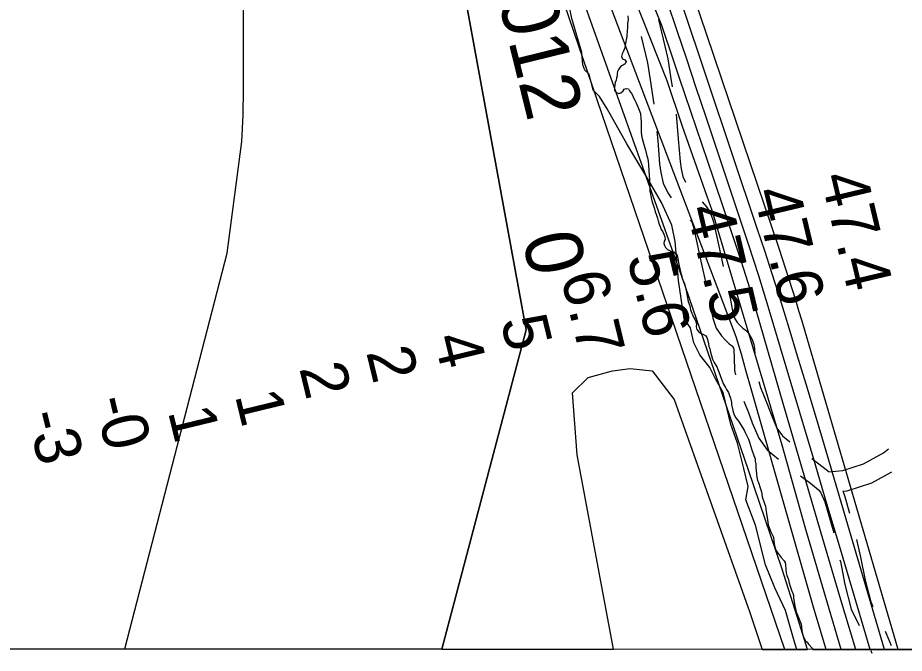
# Model space of a CAD drawing. Extents: x 3250478 to 3288318, y 788638 to 816472.
# Drawn here: x 3278442 to 3279729, y 794010 to 794932 of the extents above; entities that cross this region are included whole.
import ezdxf

# ---------------------------------------------------------------- set-up
doc = ezdxf.new("R2010")
doc.units = 0
for name, color, linetype in [('V-GRID-FRAM', 7, 'Continuous'), ('V-RIVR-EDGE', 7, 'Continuous'), ('V-RIVR-IDEN', 7, 'Continuous'), ('V-RIVR-RANG', 7, 'Continuous'), ('V-ROAD-CNTR', 7, 'Continuous'), ('V-SITE-VEGE', 7, 'Continuous'), ('V-TOPO-DPTH', 7, 'Continuous'), ('V-TOPO-MAJR', 7, 'Continuous'), ('V-TOPO-MINR', 7, 'Continuous'), ('V-TOPO-MINR-IDEN', 7, 'Continuous'), ('V-TOPO-WATR', 7, 'Continuous')]:
    doc.layers.add(name, color=color, linetype=linetype)

msp = doc.modelspace()

# ---------------------------------------------------------------- linework, layer by layer
at = {"layer": 'V-GRID-FRAM'}
msp.add_lwpolyline([(3254649.6, 812209.1), (3286070.1, 812200), (3286072.7, 794013.5), (3254636.4, 794022.7), (3254649.6, 812209.1)], dxfattribs=at)
at = {"layer": 'V-RIVR-EDGE'}
msp.add_lwpolyline([(3279573, 794015.4), (3279570, 794024.3), (3279556.2, 794071.7), (3279541, 794104.8), (3279527.2, 794138.3), (3279512.6, 794195.7), (3279498.8, 794232.7), (3279502.3, 794251.8), (3279495.8, 794277.9), (3279486.8, 794314.9), (3279476.9, 794341.8), (3279466.1, 794388.4), (3279455.3, 794407.1), (3279446.6, 794424.5), (3279431.9, 794442.8), (3279423.3, 794460.6), (3279418.5, 794482.4), (3279409.4, 794495.4), (3279401.3, 794551.1), (3279396.2, 794607.6), (3279391.5, 794631.1), (3279376.4, 794664.2), (3279353.9, 794703.4), (3279326.2, 794749.5), (3279297.6, 794800), (3279286.4, 794818.3), (3279277.2, 794827.4), (3279271.7, 794850.5), (3279265.1, 794856.2), (3279262.1, 794864), (3279260.9, 794881.8), (3279246.2, 794931.4), (3279237.6, 794974.5)], dxfattribs=at)
at = {"layer": 'V-ROAD-CNTR'}
msp.add_line((3279680.1, 794013.8), (3279681.7, 794009.7), dxfattribs=at)
for points in [[(3279372.1, 794930), (3279385.7, 794872.7), (3279389.7, 794847.1), (3279391.9, 794832)], [(3279347.1, 794905.3), (3279356.2, 794866.9), (3279360, 794842.5), (3279365.3, 794807.1)], [(3279397.5, 794792.4), (3279400.8, 794756.5), (3279403.4, 794723.9), (3279405.2, 794713.2), (3279407.6, 794701.7), (3279411.3, 794693.9)], [(3279369.7, 794767.3), (3279370.9, 794753.9), (3279373.6, 794720.2), (3279375.7, 794707.6), (3279379, 794692.1), (3279385.6, 794678.2), (3279390.6, 794671.1)], [(3279435.4, 794665.1), (3279441.7, 794658), (3279447.7, 794648.8), (3279451.7, 794635.9), (3279463, 794585.5), (3279466, 794571.5)], [(3279418.2, 794639.1), (3279420.3, 794635.9), (3279422.7, 794628.2), (3279433.7, 794579.1), (3279441.7, 794542.2)], [(3279474.5, 794532.4), (3279474.9, 794530.6), (3279480.1, 794503.8), (3279482.9, 794495.3), (3279486.7, 794489.7), (3279490.3, 794485.9), (3279494.6, 794481.7), (3279499.6, 794477.7), (3279503.6, 794473.1), (3279505.5, 794469.8), (3279508.2, 794465.1), (3279510.5, 794458.2), (3279511.4, 794452.1), (3279511.7, 794443.4)], [(3279449.6, 794503), (3279451, 794496.1), (3279455.7, 794481.9), (3279463.3, 794470.7), (3279468.9, 794464.9), (3279474.6, 794459.2), (3279478.9, 794455.9), (3279479.1, 794455.5), (3279479.5, 794455), (3279480.7, 794452.8), (3279481.3, 794451.1), (3279481.5, 794449.5), (3279481.8, 794439.3), (3279482.2, 794420.2), (3279484, 794413.8)], [(3279517.8, 794404.2), (3279520.2, 794395.8), (3279525.4, 794382.5), (3279530.4, 794370.6), (3279536.2, 794355.2), (3279543.8, 794336.6), (3279551.9, 794325.6), (3279562.5, 794316.7)], [(3279495.8, 794375.6), (3279497.6, 794371.1), (3279502.5, 794359.5), (3279508.2, 794344.3), (3279517.4, 794321.9), (3279529.8, 794304.9), (3279546, 794291.5)], [(3279619.2, 794273), (3279639.4, 794275.1), (3279669.5, 794284.9), (3279698.5, 794300.7), (3279705.8, 794306.4)], [(3279594.5, 794292.7), (3279611.1, 794280.1), (3279619.7, 794273.1)], [(3279639.3, 794244.9), (3279645.6, 794245.6), (3279681.5, 794257.2), (3279710.6, 794273.1)], [(3279578, 794267.5), (3279592.5, 794256.6), (3279604.3, 794246.9), (3279606.9, 794243.7), (3279609.1, 794239.5), (3279612, 794233), (3279613.2, 794229.7), (3279626.5, 794184.5)], [(3279639.6, 794244.9), (3279640, 794244.1), (3279641.8, 794238.8), (3279649.3, 794213.3)], [(3279659.5, 794174.7), (3279665.3, 794149.2), (3279671.8, 794116.1), (3279679.9, 794084.3), (3279683.2, 794077.7)], [(3279635.3, 794145.5), (3279635.9, 794143), (3279642.6, 794109.5), (3279651.6, 794073.9), (3279663.4, 794050.1)], [(3279700.8, 794041.8), (3279702.5, 794038.3), (3279709.5, 794021.1)]]:
    msp.add_lwpolyline(points, dxfattribs=at)
at = {"layer": 'V-SITE-VEGE'}
for p, q in [((3279328.1, 794929.5), (3279327.3, 794924.2)), ((3279327.6, 794935), (3279328.1, 794929.5)), ((3279327.2, 794918.4), (3279326.4, 794913.2)), ((3279327.3, 794924.2), (3279327.2, 794918.4)), ((3279326.3, 794905.8), (3279323.7, 794892.6)), ((3279326.4, 794913.2), (3279326.3, 794905.8)), ((3279323.2, 794888.6), (3279321.5, 794883.7)), ((3279323.7, 794892.6), (3279323.2, 794888.6)), ((3279319.5, 794880.2), (3279318.3, 794876.2)), ((3279318.3, 794876.2), (3279320, 794872.9)), ((3279321.5, 794883.7), (3279319.5, 794880.2)), ((3279318.1, 794862.5), (3279315.8, 794860.2)), ((3279320.9, 794863.8), (3279318.1, 794862.5)), ((3279320, 794872.9), (3279323.1, 794871.2)), ((3279323.9, 794865.7), (3279320.9, 794863.8)), ((3279323.1, 794871.2), (3279325.3, 794868.8)), ((3279325.3, 794868.8), (3279323.9, 794865.7)), ((3279312.6, 794854.3), (3279312.1, 794851.3)), ((3279312.1, 794851.3), (3279312.1, 794848.2)), ((3279314, 794857.4), (3279312.6, 794854.3)), ((3279315.8, 794860.2), (3279314, 794857.4)), ((3279309.1, 794838.6), (3279308.1, 794831.6)), ((3279310.8, 794841.7), (3279309.1, 794838.6)), ((3279311.3, 794844.8), (3279310.8, 794841.7)), ((3279312.1, 794848.2), (3279311.3, 794844.8)), ((3279308.1, 794831.6), (3279308.2, 794826.7)), ((3279308.2, 794826.7), (3279311, 794823.7)), ((3279311, 794823.7), (3279314.5, 794822.3)), ((3279314.5, 794822.3), (3279317.2, 794823.6)), ((3279317.2, 794823.6), (3279320.8, 794826.1)), ((3279320.8, 794826.1), (3279322.2, 794828.9)), ((3279322.2, 794828.9), (3279325.3, 794829.6)), ((3279325.3, 794829.6), (3279328.6, 794829.1)), ((3279328.6, 794829.1), (3279330.2, 794826.4)), ((3279330.2, 794826.4), (3279332.8, 794822.5)), ((3279332.8, 794822.5), (3279334.7, 794819.2)), ((3279334.7, 794819.2), (3279335.8, 794816.2)), ((3279335.8, 794816.2), (3279337.7, 794812.9)), ((3279337.7, 794812.9), (3279339, 794809.8)), ((3279339, 794809.8), (3279342.3, 794803.2)), ((3279342.3, 794803.2), (3279344.9, 794795.9)), ((3279344.9, 794795.9), (3279346.2, 794793.2)), ((3279346.2, 794793.2), (3279346.5, 794785.6)), ((3279346.5, 794785.6), (3279346.9, 794782.2)), ((3279347, 794776.4), (3279346.7, 794766.6)), ((3279346.9, 794782.2), (3279347, 794776.4)), ((3279346.7, 794766.6), (3279347.2, 794761.4)), ((3279347.2, 794761.4), (3279348.2, 794756.9)), ((3279348.2, 794756.9), (3279349.9, 794751.7)), ((3279349.9, 794751.7), (3279353.3, 794740.2)), ((3279353.3, 794740.2), (3279355.1, 794732)), ((3279355.1, 794732), (3279356.5, 794727.4)), ((3279356.5, 794727.4), (3279357.2, 794723.2)), ((3279357.2, 794723.2), (3279357.6, 794719.5)), ((3279357.6, 794719.5), (3279357.9, 794710.1)), ((3279357.9, 794710.1), (3279358.9, 794697.2)), ((3279358.9, 794697.2), (3279359.4, 794680.7)), ((3279359.4, 794680.7), (3279360.4, 794676.5)), ((3279360.4, 794676.5), (3279362.6, 794666.7)), ((3279362.6, 794666.7), (3279366.3, 794655.2)), ((3279366.3, 794655.2), (3279367.3, 794650.7)), ((3279367.3, 794650.7), (3279368.7, 794647.3)), ((3279368.7, 794647.3), (3279370.4, 794641.3)), ((3279370.4, 794641.3), (3279371.7, 794637.6)), ((3279371.7, 794637.6), (3279373.1, 794632.5)), ((3279373.1, 794632.5), (3279374.4, 794629.5)), ((3279374.4, 794629.5), (3279376.1, 794624.9)), ((3279376.1, 794624.9), (3279378.3, 794621.6)), ((3279378.3, 794621.6), (3279379.9, 794618.3)), ((3279379.9, 794618.3), (3279381.3, 794614.1)), ((3279380.2, 794607.9), (3279379.7, 794604.8)), ((3279379.7, 794604.8), (3279380.7, 794601.8)), ((3279381.7, 794610.7), (3279380.2, 794607.9)), ((3279381.3, 794614.1), (3279381.7, 794610.7)), ((3279380.7, 794601.8), (3279382.4, 794598.8)), ((3279382.4, 794598.8), (3279384.9, 794596.1)), ((3279384.9, 794596.1), (3279391.1, 794593.2)), ((3279391.1, 794593.2), (3279394.5, 794592.4)), ((3279394.5, 794592.4), (3279397.3, 794590.1)), ((3279397.3, 794590.1), (3279399.2, 794587.4)), ((3279399.2, 794587.4), (3279400.7, 794579.8)), ((3279400.7, 794579.8), (3279401.1, 794576.4)), ((3279401.1, 794576.4), (3279404.3, 794561.5)), ((3279404.3, 794561.5), (3279405.9, 794557)), ((3279405.9, 794557), (3279406.6, 794553.9)), ((3279406.6, 794553.9), (3279408.3, 794549.4)), ((3279408.3, 794549.4), (3279409.6, 794546.7)), ((3279409.6, 794546.7), (3279410.7, 794542.1)), ((3279410.7, 794542.1), (3279411.7, 794538.5)), ((3279411.7, 794538.5), (3279412.5, 794533.6)), ((3279412.5, 794533.6), (3279413.5, 794528.1)), ((3279413.5, 794528.1), (3279415.3, 794520.5)), ((3279415.3, 794520.5), (3279417.3, 794514.2)), ((3279417.3, 794514.2), (3279418.7, 794508.4)), ((3279418.7, 794508.4), (3279423, 794497.8)), ((3279423, 794497.8), (3279424.6, 794494.8)), ((3279424.6, 794494.8), (3279426.3, 794491.5)), ((3279426.3, 794491.5), (3279427, 794488.1)), ((3279427, 794488.1), (3279426.8, 794483.6)), ((3279426.8, 794483.6), (3279427.8, 794479.9)), ((3279427.8, 794479.9), (3279430.4, 794476.3)), ((3279430.4, 794476.3), (3279433.2, 794474.6)), ((3279433.2, 794474.6), (3279437.5, 794472.6)), ((3279437.5, 794472.6), (3279440.7, 794470.8)), ((3279440.7, 794470.8), (3279442.3, 794468.1)), ((3279442.3, 794468.1), (3279443.3, 794465.1)), ((3279443.3, 794465.1), (3279444.7, 794459)), ((3279444.7, 794459), (3279445.1, 794455)), ((3279445.1, 794455), (3279446.4, 794452)), ((3279446.4, 794452), (3279447.5, 794447.1)), ((3279447.5, 794447.1), (3279450.2, 794436.8)), ((3279450.2, 794436.8), (3279452.8, 794431.7)), ((3279452.8, 794431.7), (3279457, 794424.8)), ((3279457, 794424.8), (3279458, 794421.8)), ((3279458, 794421.8), (3279459.4, 794418.4)), ((3279459.4, 794418.4), (3279463.4, 794407.5)), ((3279463.4, 794407.5), (3279466.6, 794400.3)), ((3279466.6, 794400.3), (3279469.2, 794395.5)), ((3279469.2, 794395.5), (3279470.5, 794392.8)), ((3279470.5, 794392.8), (3279473.4, 794388.3)), ((3279473.4, 794388.3), (3279474.7, 794385.2)), ((3279474.7, 794385.2), (3279476.4, 794380.1)), ((3279476.4, 794380.1), (3279477.8, 794374)), ((3279477.8, 794374), (3279477.9, 794371)), ((3279477.9, 794371), (3279479, 794366.7)), ((3279479, 794366.7), (3279479.7, 794362.4)), ((3279479.7, 794362.4), (3279480.7, 794358.8)), ((3279480.7, 794358.8), (3279481.7, 794355.8)), ((3279481.7, 794355.8), (3279484.3, 794351.6)), ((3279484.3, 794351.6), (3279488.1, 794346.8)), ((3279488.1, 794346.8), (3279496.5, 794333.6)), ((3279496.5, 794333.6), (3279497.8, 794330.5)), ((3279497.8, 794330.5), (3279500.4, 794325.4)), ((3279500.4, 794325.4), (3279502.7, 794320.6)), ((3279502.7, 794320.6), (3279504, 794316.4)), ((3279504, 794316.4), (3279506.8, 794306.6)), ((3279506.8, 794306.6), (3279507.8, 794303.6)), ((3279507.8, 794303.6), (3279510.4, 794297)), ((3279510.4, 794297), (3279512.1, 794291.8)), ((3279512.1, 794291.8), (3279512.5, 794288.5)), ((3279512.5, 794288.5), (3279513.3, 794284.2)), ((3279513.3, 794284.2), (3279513.1, 794279.3)), ((3279513.1, 794279.3), (3279514.7, 794265.6)), ((3279514.7, 794265.6), (3279515.8, 794260.7)), ((3279515.8, 794260.7), (3279517.1, 794257.7)), ((3279517.1, 794257.7), (3279519.5, 794250.1)), ((3279519.5, 794250.1), (3279521.5, 794244.1)), ((3279521.5, 794244.1), (3279522.3, 794237)), ((3279522.3, 794237), (3279526, 794227.4)), ((3279526, 794227.4), (3279527.3, 794223.4)), ((3279527.3, 794223.4), (3279527.8, 794219.2)), ((3279527.8, 794219.2), (3279528.5, 794215.5)), ((3279528.5, 794215.5), (3279530.1, 794203.3)), ((3279530.1, 794203.3), (3279531.3, 794196)), ((3279531.3, 794196), (3279534.4, 794187)), ((3279534.4, 794187), (3279537.2, 794182.2)), ((3279537.2, 794182.2), (3279539.1, 794178.4)), ((3279539.1, 794178.4), (3279539.3, 794172.6)), ((3279539.3, 794172.6), (3279540.2, 794165.9)), ((3279540.2, 794165.9), (3279542.4, 794159.6)), ((3279542.4, 794159.6), (3279544, 794156.4)), ((3279544, 794156.4), (3279550, 794149)), ((3279550, 794149), (3279554.4, 794143.8)), ((3279554.4, 794143.8), (3279555.9, 794141.3)), ((3279555.9, 794141.3), (3279556.5, 794138.1)), ((3279556.5, 794138.1), (3279556.8, 794131.4)), ((3279556.8, 794131.4), (3279557.4, 794126.3)), ((3279557.4, 794126.3), (3279558.3, 794122.8)), ((3279558.3, 794122.8), (3279560.5, 794116.7)), ((3279560.5, 794116.7), (3279561.1, 794113.5)), ((3279561.1, 794113.5), (3279563.6, 794105.8)), ((3279563.6, 794105.8), (3279565.7, 794100.1)), ((3279565.7, 794100.1), (3279567, 794097.2)), ((3279567, 794097.2), (3279567.9, 794093.7)), ((3279567.9, 794093.7), (3279567.9, 794089.9)), ((3279567.9, 794089.9), (3279569.1, 794084.8)), ((3279569.1, 794084.8), (3279569.4, 794080.6)), ((3279569.4, 794080.6), (3279571.8, 794070.1)), ((3279571.8, 794070.1), (3279575.3, 794061.8)), ((3279575.3, 794061.8), (3279579, 794052.2)), ((3279579, 794052.2), (3279579.6, 794048)), ((3279579.6, 794048), (3279580.2, 794042)), ((3279580.2, 794042), (3279581.4, 794036.6)), ((3279581.4, 794036.6), (3279583.6, 794031.1)), ((3279583.6, 794031.1), (3279585.5, 794027.9)), ((3279585.5, 794027.9), (3279588, 794026)), ((3279588, 794026), (3279589.6, 794023.1)), ((3279589.6, 794023.1), (3279595.9, 794016)), ((3279595.9, 794016), (3279596.1, 794015.4)), ((3279596.1, 794015.4), (3286072.7, 794013.5))]:
    msp.add_line(p, q, dxfattribs=at)
at = {"layer": 'V-TOPO-DPTH'}
for points in [[(3279522.7, 794015.4), (3279588.3, 794015.4), (3279573.8, 794061.7), (3279550.8, 794133.3), (3279527, 794204.6), (3279502.7, 794275.7), (3279411.4, 794541.6), (3279128.4, 795335.7), (3279124.3, 795347.8), (3278841.2, 796159.2)], [(3279057.6, 794015.6), (3278260.3, 794016.3), (3278403.9, 794831.3), (3278416.4, 794942.1), (3278416.5, 794961.6), (3278416.1, 794981.1), (3278415.2, 795000.6), (3278414, 795020), (3278405.8, 795125.3), (3278400.6, 795197.4), (3278395.9, 795269.5), (3278391.9, 795341.7), (3278388.5, 795413.9), (3278377.3, 795677.1), (3278398.9, 795790.4), (3278405.1, 795830.1), (3278409.6, 795870), (3278411.5, 795910.1), (3278411.7, 795950.3), (3278410.5, 795990.6), (3278409.3, 796030.9), (3278408.8, 796048.2)], [(3278859.6, 795871.1), (3278877.2, 795822.7), (3278881, 795812.1), (3278884.7, 795801.4), (3278888.4, 795790.7), (3278892, 795780), (3278914.1, 795712.9), (3278928.2, 795668.4), (3278941.5, 795623.7), (3278953.6, 795578.7), (3278965, 795533.5), (3279061.2, 795129.2), (3279180.3, 794479.5), (3279057.6, 794015.6)], [(3278859.6, 795871.1), (3278877.2, 795822.7), (3278881, 795812.1), (3278884.7, 795801.4), (3278888.4, 795790.7), (3278892, 795780), (3278914.1, 795712.9), (3278928.2, 795668.4), (3278941.5, 795623.7), (3278953.6, 795578.7), (3278965, 795533.5), (3279061.2, 795129.2), (3279180.3, 794479.5), (3279057.6, 794015.6), (3279306.6, 794015.5)], [(3279522.7, 794015.4), (3279306.6, 794015.5), (3279253.9, 794298), (3279247.5, 794387.7), (3279269.9, 794410.2), (3279305.2, 794419.8), (3279330.8, 794423), (3279362.8, 794419.8), (3279394.9, 794378.1), (3279503.9, 794070.3), (3279522.7, 794015.4)], [(3279306.6, 794015.5), (3279253.9, 794298), (3279247.5, 794387.7), (3279269.9, 794410.2), (3279305.2, 794419.8), (3279330.8, 794423), (3279362.8, 794419.8), (3279394.9, 794378.1), (3279503.9, 794070.3), (3279522.7, 794015.4)]]:
    msp.add_lwpolyline(points, dxfattribs=at)
at = {"layer": 'V-TOPO-MAJR'}
msp.add_lwpolyline([(3279658.2, 794015.4), (3279635.3, 794092.1), (3279607.9, 794184.3), (3279580.8, 794276.6), (3279554, 794368.9), (3279508.4, 794526.2), (3279504.4, 794539.9), (3279495.9, 794567.3), (3279491.4, 794580.9), (3279468.1, 794650.8), (3279451.9, 794699.3), (3279435.6, 794747.9), (3279419.2, 794796.3), (3279402.7, 794844.8), (3279394.3, 794869.5), (3279377.1, 794921.1), (3279092.3, 795626.9), (3279080.4, 795649.8), (3279069.9, 795673.5), (3279027.2, 795783.4), (3279018.2, 795806.7), (3279009.4, 795830.1), (3279000.8, 795853.6)], dxfattribs=at)
at = {"layer": 'V-TOPO-MINR'}
for points in [[(3279588.3, 794015.4), (3279573.8, 794061.7), (3279550.8, 794133.3), (3279527, 794204.6), (3279502.7, 794275.7), (3279411.4, 794541.6), (3279128.4, 795335.7), (3279124.3, 795347.8), (3278841.2, 796159.2)], [(3279555.5, 794015.4), (3279153.9, 795192.3), (3279152.6, 795194.3), (3279151.6, 795196.4), (3279150.7, 795198.6), (3279149.8, 795200.8), (3279149, 795203.1), (3279148.3, 795205.4), (3278840.2, 796077.4)], [(3279637.1, 794015.4), (3279619.5, 794074.3), (3279585.1, 794193), (3279551.3, 794311.9), (3279449.8, 794652.4), (3279442.7, 794672.9), (3279407.1, 794774.4), (3279384.5, 794841), (3279017.6, 795767.2), (3279006.9, 795797.1), (3278996.1, 795826.9), (3278985.5, 795856.8)], [(3279615.1, 794015.4), (3279597, 794076.9), (3279563.9, 794191.8), (3279506.7, 794393.7), (3279499.5, 794418.9), (3279492.3, 794444.1), (3279484.9, 794469.3), (3279117.5, 795435.9), (3279110, 795454.4), (3279103.1, 795473.2), (3278991.2, 795801.4), (3278987.4, 795812.6), (3278983.5, 795823.8), (3278979.6, 795835.1)], [(3279679.3, 794015.4), (3279636.2, 794160.7), (3279616.5, 794226.9), (3279596.8, 794293.1), (3279577.1, 794359.3), (3279557.4, 794425.5), (3279531.4, 794513.1), (3279524.6, 794535.5), (3279517.7, 794557.8), (3279510.5, 794580.1), (3279503.2, 794602.2), (3279440.7, 794789.4), (3279426.9, 794830.7), (3279413, 794872.1), (3279399.2, 794913.5), (3279385.3, 794954.9), (3279382, 794964.8), (3279370, 795001.3), (3279057.9, 795749.5), (3279036.6, 795800.1), (3279029.8, 795816.8), (3279023.1, 795833.5)], [(3279699.9, 794015.4), (3279610.3, 794319.6), (3279598.2, 794360.1), (3279586.2, 794400.6), (3279573.9, 794441.1), (3279561.7, 794481.6), (3279556.3, 794499.2), (3279546.5, 794530.8), (3279536.5, 794562.3), (3279526.3, 794593.8), (3279515.9, 794625.2), (3279405.9, 794952.9), (3279397.5, 794977.9), (3279389.2, 795002.9), (3279380.9, 795027.9), (3279372.6, 795052.9), (3279370.2, 795060.3), (3279363.3, 795081.7), (3279052.5, 795802.8), (3279045.8, 795817.3), (3279041.4, 795827.1), (3279037.3, 795836.9)], [(3279720, 794015.4), (3279584.9, 794476.8), (3279580.4, 794492), (3279575.9, 794507.1), (3279571.2, 794522.2), (3279566.6, 794537.2), (3279561.8, 794552.3), (3279557, 794567.3), (3279552, 794582.3), (3279547.1, 794597.2), (3279369.2, 795124), (3279366.7, 795131.4), (3279364.3, 795138.7), (3279361.9, 795146.1), (3279359.5, 795153.4), (3279358.6, 795156), (3279356.7, 795162.1), (3279354.7, 795168.2), (3279352.9, 795174.3), (3279351, 795180.4), (3279349.3, 795186), (3279056, 795831.8)], [(3278597.9, 794016.3), (3278746.4, 794590.5), (3278767.7, 794752.8), (3278769.3, 794790.9), (3278769.9, 794829.1), (3278769.7, 795058.1), (3278753.7, 795211.3), (3278749.1, 795241.9)]]:
    msp.add_lwpolyline(points, dxfattribs=at)
at = {"layer": 'V-TOPO-WATR'}
for points in [[(3279057.6, 794015.6), (3279180.3, 794479.5), (3279061.2, 795129.2), (3278965, 795533.5), (3278953.6, 795578.7), (3278941.5, 795623.7), (3278928.2, 795668.4), (3278914.1, 795712.9), (3278892, 795780), (3278888.4, 795790.7), (3278884.7, 795801.4), (3278881, 795812.1), (3278877.2, 795822.7), (3278859.6, 795871.1)], [(3279306.6, 794015.5), (3279253.9, 794298), (3279247.5, 794387.7), (3279269.9, 794410.2), (3279305.2, 794419.8), (3279330.8, 794423), (3279362.8, 794419.8), (3279394.9, 794378.1), (3279503.9, 794070.3), (3279522.7, 794015.4)]]:
    msp.add_lwpolyline(points, dxfattribs=at)

# ---------------------------------------------------------------- texts
at = {"layer": 'V-RIVR-IDEN'}
msp.add_text('2012', height=83, rotation=283.8266, dxfattribs=at).set_placement((3279124.4, 795019.2))
at = {"layer": 'V-RIVR-RANG'}
for s, rotation, p in [('47.4', 283.3683, (3279607, 794701.5)), ('47.6', 283.3683, (3279509.4, 794679.9)), ('47.5', 283.3683, (3279412.6, 794654.7)), ('5.6', 283.6536, (3279326.1, 794584.7)), ('6.7', 283.6536, (3279229.9, 794557)), ('5', 283.6536, (3279142.6, 794492.8)), ('4', 283.6536, (3279045.8, 794467.7)), ('2', 283.6536, (3278947.8, 794447.1)), ('2', 283.6536, (3278850.6, 794423.8)), ('1', 283.6536, (3278757.3, 794384.3)), ('-0', 283.6536, (3278553.1, 794377.5)), ('1', 283.6536, (3278660.1, 794360.9)), ('-3', 283.6536, (3278455.3, 794356.5))]:
    msp.add_text(s, height=67, rotation=rotation, dxfattribs=at).set_placement(p)
at = {"layer": 'V-TOPO-MINR-IDEN'}
msp.add_text('0', height=83, rotation=282.0514, dxfattribs=at).set_placement((3279174.2, 794613.3))

doc.saveas('drawing.dxf')
